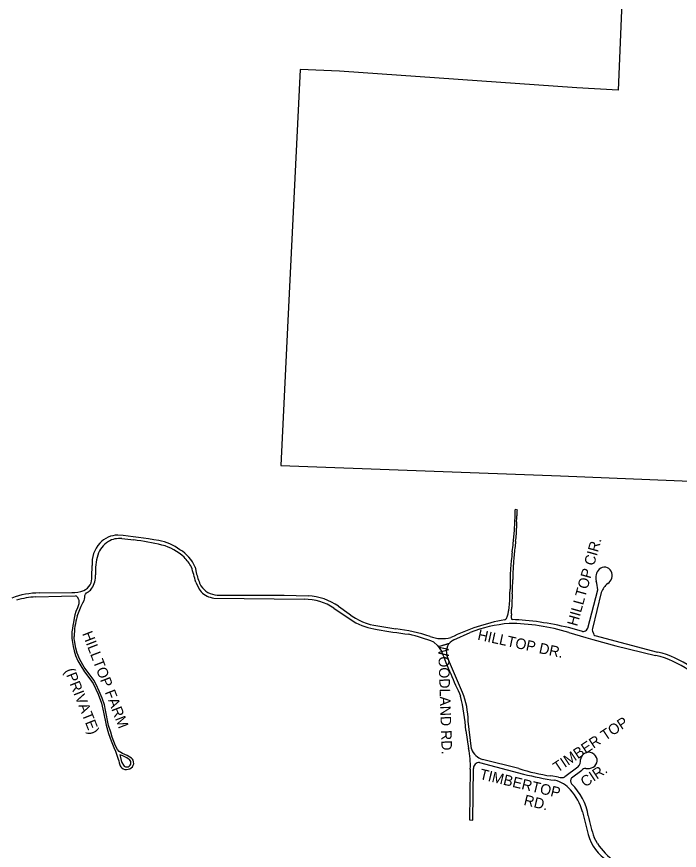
# Model space of a CAD drawing. Extents: x 0 to 712119, y 0 to 761125.
# Drawn here: x 691516 to 694653, y 738736 to 742682 of the extents above; entities that cross this region are included whole.
import ezdxf

# ---------------------------------------------------------------- set-up
doc = ezdxf.new("R2010")
doc.units = 0
for name, color, linetype in [('city boundary', 7, 'Continuous'), ('PAVED ROADS', 7, 'Continuous'), ('street names', 7, 'Continuous')]:
    doc.layers.add(name, color=color, linetype=linetype)

msp = doc.modelspace()

# ---------------------------------------------------------------- linework, layer by layer
at = {"layer": 'city boundary'}
msp.add_lwpolyline([(694419.7, 743656.6), (694363.2, 742335.3), (694168.8, 742346.2), (693044.1, 742425.1), (692858.9, 742432.1), (692798.2, 741210.6), (692765.8, 740557.7), (694091.2, 740509.1), (695398.1, 740455.3)], dxfattribs=at)
at = {"layer": 'PAVED ROADS'}
for points in [[(693877, 740350.5), (693885.6, 740348.6)], [(692014, 740211.8), (692070, 740206)], [(691871.9, 740032.1), (691873.1, 740083.8)], [(692360.4, 740075.8), (692368, 740043.5)], [(692364.2, 740006), (692379.3, 739972.7), (692389.8, 739959.1)], [(694219.6, 739788.2), (694266.8, 739969.8)], [(691606.1, 739935.6), (691727.4, 739939.4), (691793.9, 739940.3)], [(691624.1, 739954.3), (691776.7, 739955.9)], [(691802, 739843.9), (691821.6, 739892), (691829.5, 739908.3), (691835.6, 739918.8), (691837.6, 739924.2), (691837.8, 739933), (691838.8, 739942.7), (691841.5, 739949.1), (691845.9, 739954.2), (691851.9, 739957.7), (691856.2, 739960.3)], [(691802.6, 739935.7), (691809.3, 739924.3)], [(692449.1, 739930.2), (692878, 739924.7)], [(692465.2, 739944.5), (692782.6, 739943.8), (692896.6, 739940.1)], [(694283.5, 739956.4), (694241.8, 739785.9)], [(691810.9, 739902.8), (691804.2, 739883.8), (691796.5, 739866.3), (691791.9, 739850.5), (691787.3, 739834.3), (691784.4, 739815.3), (691781.2, 739800.6), (691779.5, 739786.6), (691777.6, 739770.9), (691777.4, 739748.5), (691777.4, 739739.9), (691778, 739728.9), (691783, 739700.5), (691788, 739680), (691794.5, 739658), (691805, 739633.5), (691818.9, 739608.7), (691837, 739581.6), (691862.5, 739548.5), (691877.5, 739526), (691901.5, 739474.5), (691917, 739432), (691926.5, 739390.3), (691940.2, 739328.6), (691950.5, 739289.5), (691962.5, 739255), (691976.5, 739223), (691984.5, 739205), (691997, 739167), (691999, 739159), (692001, 739150.5), (692002, 739145.5), (692003.5, 739140), (692005.5, 739136), (692009, 739132), (692014.5, 739126), (692020.5, 739121.5), (692028, 739119), (692035.5, 739118.5), (692043.5, 739120), (692051, 739122), (692058, 739126), (692063.5, 739131), (692068, 739139), (692070.5, 739146), (692069.5, 739155), (692067, 739162.5), (692064, 739168), (692059.5, 739173), (692038.5, 739185), (692017.5, 739195), (692001.5, 739204), (691993.5, 739213), (691984.5, 739231), (691968.5, 739271), (691961, 739295.5), (691951.4, 739327), (691935.8, 739399), (691931.5, 739425), (691920, 739456.5), (691907, 739490), (691892.5, 739520.9), (691881.1, 739541), (691836.1, 739602.4), (691814.2, 739639.4), (691803, 739669.5), (691795.9, 739692.6), (691789.1, 739729.1), (691788.5, 739738.5), (691788.6, 739748.5)], [(693039.2, 739891.7), (693089.7, 739856.2)], [(693018.1, 739882.6), (693108.9, 739820.4)], [(691802, 739843.9), (691802, 739843.9)], [(693226.3, 739798.5), (693311.1, 739784.9)], [(694195.4, 739772.5), (694195.4, 739772.5)], [(694242.2, 739772.8), (694246.8, 739761.8)], [(693586, 739731.8), (693663.2, 739766.9)], [(694130.4, 739767.1), (694210.1, 739744), (694244, 739734.2), (694353, 739704.3), (694540.8, 739658.8)], [(694253.6, 739752.2), (694550.4, 739674.7)], [(693491.5, 739721.6), (693508.1, 739705.7), (693527.2, 739678.7)], [(693626.6, 739483.7), (693565.5, 739626.7), (693552.5, 739659.4)], [(693669, 739215.9), (693653.3, 739347.5)], [(693641.8, 739303.8), (693654.9, 739218.5)], [(692044.5, 739169.5), (692037.5, 739174), (692024.5, 739180.5), (692018, 739183.5), (692005, 739187.5), (692007.5, 739175.5), (692010, 739161.5), (692013.5, 739152.5), (692021, 739138.5)], [(692044.5, 739169.5), (692044.5, 739169.5)], [(693707.6, 739152.3), (693916.1, 739097.2)], [(693893.9, 739122.6), (693722.2, 739166)], [(693663.4, 739120.4), (693659.6, 738879.7), (693676.2, 738879), (693678.6, 739123.7)], [(694173.5, 739130.2), (694111.8, 739083.4)], [(694143, 739078.8), (694191.3, 739115.4)], [(694081, 739082.9), (694045.4, 739088)], [(694194.9, 738917.7), (694217.2, 738829.7)], [(694265.4, 738768.1), (694250.2, 738797.5)]]:
    msp.add_lwpolyline(points, dxfattribs=at)
for centre, radius, start, end in [((688779.9, 740506.5), 5099.5, 357.7598, 358.0036), ((688784.7, 740506.3), 5094.7, 358.0036, 358.2477), ((694048.8, 740320.7), 165.5, 170.312, 180.3831), ((691791.4, 740389.5), 2085.7, 357.0099, 357.7373), ((694645.7, 740266.8), 763.1, 178.2253, 180.3915), ((692881.1, 740313.3), 1002.2, 358.6899, 0.3597), ((692909.6, 740313.7), 965, 354.5889, 356.4681), ((690565.4, 740453.5), 3313.4, 356.552, 357.0099), ((693466.5, 740258.7), 416.2, 356.4225, 0.3927), ((691994.6, 740113.4), 114.6, 89.8197, 137.8093), ((692003.6, 740104.8), 107.5, 84.4732, 119.9439), ((691830, 738238.6), 1996.2, 79.6432, 85.2592), ((691685.3, 737768.8), 2467.4, 77.8679, 81.0293), ((690879.2, 740506), 3004.5, 353.9854, 354.589), ((693206.1, 740285.2), 677.8, 352.7109, 355.5623), ((692013.5, 740095.1), 140.9, 137.4806, 184.6302), ((692014.5, 740095.3), 121.3, 122.1712, 161.4001), ((692142.3, 739958.4), 248.3, 53.8911, 79.2086), ((692144.2, 739949.2), 239.4, 46.6601, 75.5806), ((691701.1, 740422.6), 2178.4, 352.7787, 353.9019), ((695323.6, 740014.3), 1457, 172.7114, 174.0381), ((692144.9, 740060.5), 256, 163.3281, 184.3979), ((692207.1, 740016.2), 164.5, 21.2326, 60.2545), ((695971.2, 739881.5), 2125.9, 172.7787, 173.9297), ((695781.1, 739946), 1918.9, 174.4311, 175.4352), ((710055.7, 738554.2), 16261.2, 174.31263, 174.43111), ((692169.7, 739983.1), 197.3, 28.3626, 45.2791), ((695458, 739935.1), 1609.9, 173.8924, 174.7761), ((694919.4, 740016.9), 1054.3, 175.5507, 177.0404), ((688400.1, 738873.7), 4122.7, 15.9413, 16.9677), ((698210.4, 739953.2), 4358.3, 178.6365, 178.9633), ((694246.7, 740045.8), 393.5, 174.7749, 178.3888), ((695451.8, 739989.4), 1587.5, 177.0402, 178.0296), ((694314.7, 740026.8), 57.2, 134.9183, 197.0134), ((694298.4, 740039.6), 36.8, 29.3508, 130.9309), ((694289.6, 740037), 45.8, 302.68, 26.7382), ((691808.2, 740025.1), 64.1, 292.9194, 6.2804), ((691781.4, 740035.4), 108.3, 326.9981, 2.889), ((692669.8, 740120.2), 311.4, 194.2776, 205.1713), ((709664.3, 739745.9), 15814.1, 178.96328, 179.05335), ((692871.2, 740026.3), 993.6, 357.9965, 359.5091), ((695032, 740007.7), 1167.3, 178.2214, 179.509), ((694111.6, 739964.3), 155.3, 2.0079, 17.1319), ((691797.9, 740034.6), 94.4, 308.1065, 321.9791), ((692468.7, 740041.1), 96.7, 213.4634, 267.9126), ((686311.8, 740071), 7540.7, 358.99674, 359.25572), ((704396.8, 739836.1), 10545.8, 179.07057, 179.25575), ((689803.8, 740157.8), 4063.8, 357.0745, 357.6558), ((694373.4, 739922.8), 96, 127.9951, 159.544), ((691622.9, 739594.2), 360.1, 89.812, 111.2798), ((691619.6, 739591), 344.9, 92.242, 107.5137), ((691778.2, 740109.2), 153.3, 269.4302, 290.9967), ((691795.5, 739932.8), 7.62, 22.388, 102.4719), ((692463.8, 740035.3), 106.2, 225.8498, 262.0203), ((692883.7, 739668.2), 272.3, 55.1715, 87.2896), ((693344.3, 739948.1), 507.1, 356.2037, 358.9757), ((697199.6, 739779.8), 3341.7, 177.0745, 177.7813), ((691775.5, 739911.1), 36.4, 346.8763, 21.3982), ((692876.9, 739666.9), 257.8, 56.7877, 89.7541), ((693345.7, 739948.8), 505.8, 351.344, 353.3316), ((693379.3, 739945.7), 472, 353.2268, 356.2051), ((695647.5, 739849.4), 1788, 178.0845, 178.7993), ((693257.3, 740062.5), 265.8, 230.9122, 263.3031), ((693705.2, 739883.7), 140.2, 344.5507, 348.3719), ((693560, 739916.2), 289, 347.8677, 351.3453), ((694042.2, 739837), 184.7, 174.3879, 177.3581), ((693604.7, 739879.9), 254.8, 354.3882, 356.5423), ((693077.9, 739903.3), 782.1, 357.1653, 358.7994), ((692117.7, 739750.8), 329.1, 163.5849, 180.3995), ((693264.6, 740088.5), 310, 239.8607, 262.1497), ((694005, 738861.2), 982.8, 100.4672, 116.1717), ((693827.7, 739833.2), 5.65, 258.099, 330.9544), ((693796.5, 739857.2), 45, 323.3812, 334.1938), ((693796.4, 739858.5), 45.6, 332.9083, 344.5929), ((693958.9, 739840.7), 101.4, 177.3065, 180.4903), ((693892.9, 739840.1), 35.4, 180.4701, 189.5564), ((693876.2, 739839.1), 18.8, 194.9232, 211.747), ((693861.5, 739829.1), 1.32, 174.1659, 243.3241), ((693868.4, 739369.7), 458.3, 90.7914, 90.944), ((693868.4, 739369.7), 458.3, 82.8673, 90.7914), ((693785.8, 738371), 1460.1, 73.7097, 84.5152), ((693856.7, 743459.4), 3732.3, 260.2122, 262.5485), ((693214.9, 738986.6), 804.1, 71.2459, 83.1253), ((693909.5, 739132), 681, 95.2461, 111.2038), ((693844.8, 738841.8), 968.3, 72.8469, 89.8551), ((694198.6, 739778), 6.41, 239.8627, 322.1083), ((694202.2, 739791.8), 17.8, 274.5847, 348.4118), ((694281.1, 739780.7), 39.7, 172.4758, 191.3888), ((693131.5, 738775.5), 1012.3, 69.1715, 76.2178), ((693530.6, 739911.2), 172.9, 250.6983, 283.7172), ((694260.2, 739764.1), 13.5, 189.7699, 241.0537), ((693610.3, 739676.6), 60.4, 113.805, 196.566), ((696752.5, 740925.6), 3457.9, 201.136, 204.971), ((694435.6, 739213.7), 457.4, 54.7184, 76.7057), ((694441.3, 739222.4), 465.3, 54.8646, 76.4377), ((692800.7, 739262.1), 842.1, 2.8447, 14.001), ((693300.5, 739348.9), 352.8, 359.783, 22.4678), ((693337.8, 739141.4), 326.3, 356.3066, 13.6696), ((693746.8, 739245.6), 83.3, 200.9501, 252.8005), ((694224.5, 739161.2), 39.2, 47.6981, 172.6848), ((694227.7, 739161.7), 36.8, 299.5257, 50.7996), ((692036.8, 739150.9), 20.1, 218.1394, 67.5317), ((693707.1, 739123.8), 28.5, 89.074, 180.0331), ((694136.3, 739162.8), 49.4, 318.7997, 3.9237), ((694178.4, 740020), 941.4, 252.4079, 261.8776), ((694209.5, 739099.3), 24.3, 88.3275, 138.6369), ((694217.8, 739186.7), 63.5, 263.1731, 296.1986), ((694213.4, 740201.3), 1143.4, 254.9293, 262.5114), ((694027.2, 738924.2), 148.2, 41.4489, 75.4852), ((694095.8, 739129), 48.4, 252.301, 289.4206), ((694160.8, 739064.5), 22.8, 141.1554, 216.7778), ((693955.2, 738855.7), 247.6, 14.4986, 42.3007), ((693965.5, 738860.9), 259.7, 8.4083, 47.0262), ((694834.1, 739012.1), 622.1, 190.4918, 200.1787), ((694433.3, 738872), 220.2, 191.066, 232.277), ((694540.2, 738954.1), 331.8, 214.0925, 234.4234)]:
    msp.add_arc(centre, radius, start, end, dxfattribs=at)

# ---------------------------------------------------------------- texts
at = {"layer": 'street names'}
for s, rotation, p in [('HILLTOP CIR.', 74.3388, (694169.3, 739794)), ('HILLTOP FARM', 291.1044, (691825.5, 739762.3)), ('HILLTOP DR.', 347.7537, (693695.2, 739733.4)), ('WOODLAND RD.', 271.8848, (693511, 739716.5)), ('(PRIVATE)', 291.6461, (691741.3, 739587.4)), ('TIMBER TOP', 33.7516, (694076.7, 739102.7)), ('TIMBERTOP', 346.4944, (693704.4, 739074.3)), ('CIR.', 33.7516, (694206.8, 739033)), ('RD.', 346.4944, (693913.7, 738951.7))]:
    msp.add_text(s, height=50, rotation=rotation, dxfattribs=at).set_placement(p)

doc.saveas('drawing.dxf')
